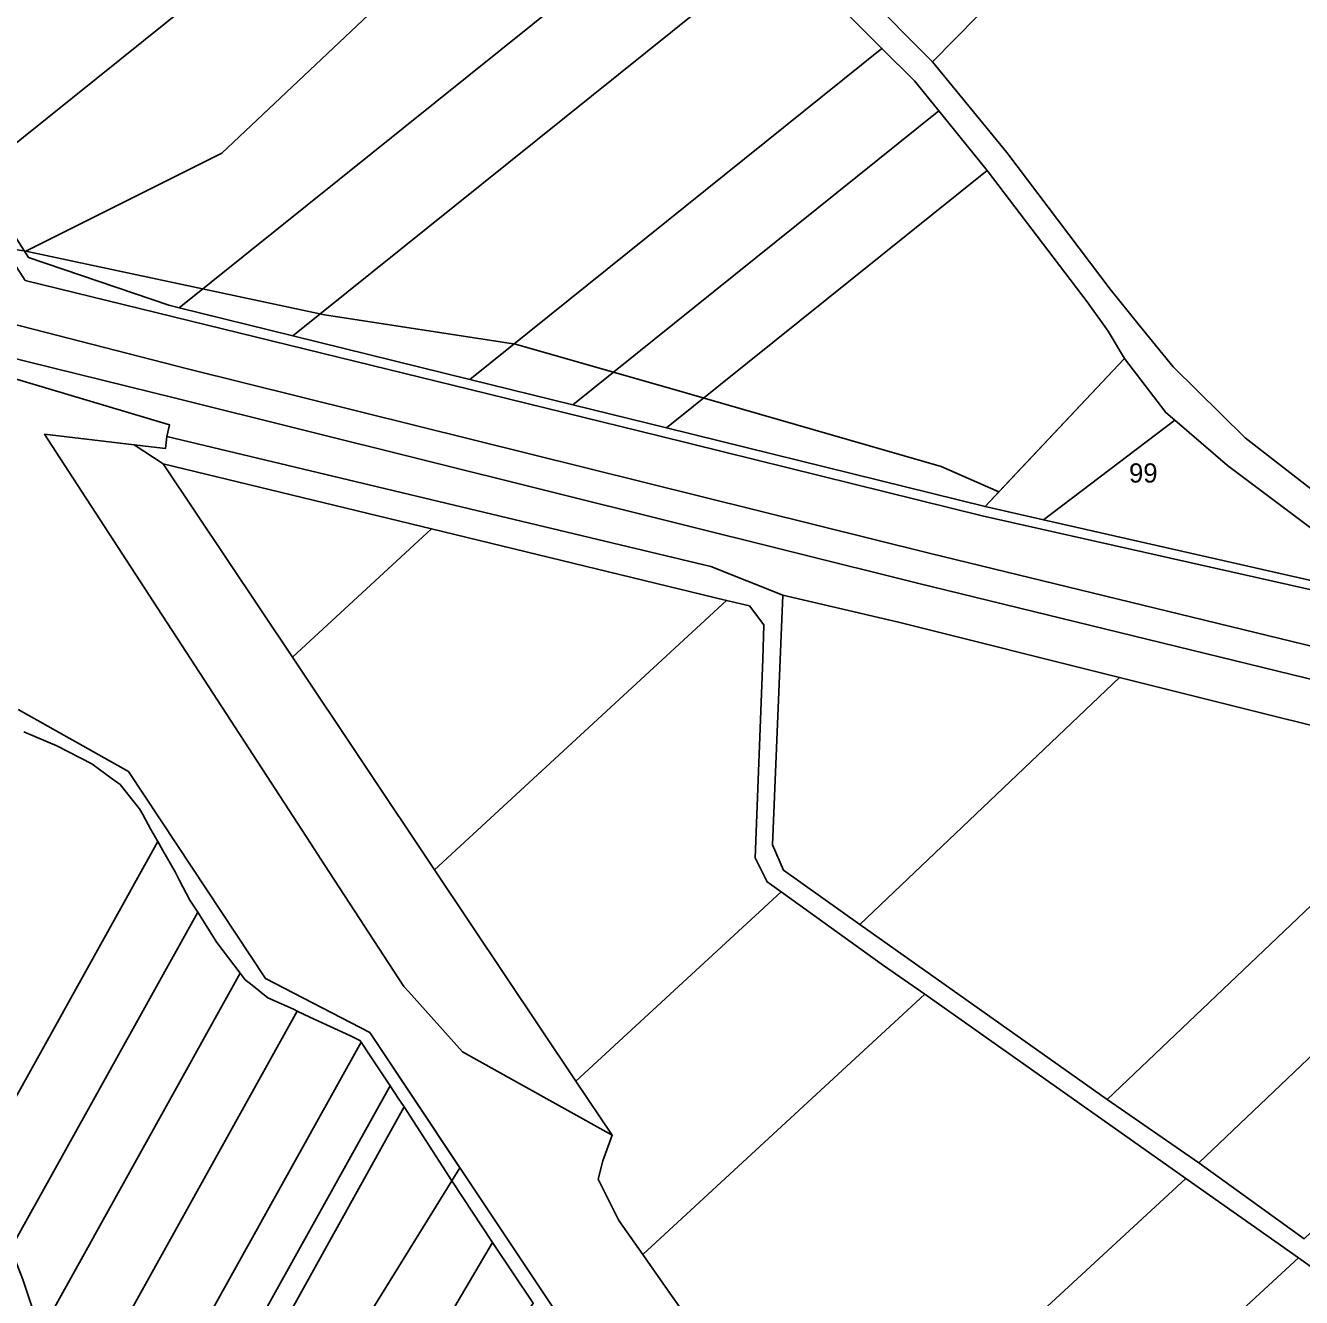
# Model space of a CAD drawing. Extents: x -545779 to -541342, y -1153413 to -1149956.
# Drawn here: x -543590.9 to -543258.3, y -1151443.3 to -1151111.8 of the extents above; entities that cross this region are included whole.
import ezdxf

# ---------------------------------------------------------------- set-up
doc = ezdxf.new("R2010")
doc.units = 0
for name, color, linetype in [('95560013', 7, 'Continuous'), ('95620013', 7, 'Continuous'), ('95630013', 7, 'Continuous'), ('95640013', 7, 'Continuous'), ('95660013', 7, 'Continuous')]:
    doc.layers.add(name, color=color, linetype=linetype)

msp = doc.modelspace()

# ---------------------------------------------------------------- linework, layer by layer
at = {"layer": '95560013'}
for points in [[(-543191.79, -1150924.95), (-543167.01, -1150930.79), (-543260.76, -1151026.06), (-543354.5, -1151121.33), (-543361.45, -1151114.32), (-543369.81, -1151105.87), (-543280.8, -1151015.41)], [(-543354.5, -1151121.33), (-543260.76, -1151026.06), (-543167.01, -1150930.79), (-542994.21, -1150971.47), (-543123.69, -1151103.06), (-543253.17, -1151234.66), (-543273, -1151219.27), (-543291.79, -1151200.81), (-543300.61, -1151189.88), (-543308.17, -1151180.51), (-543335.16, -1151144.92)], [(-543630.2, -1151097.88), (-543573.06, -1151053.18), (-543432.69, -1150939.38), (-543431.56, -1150970.58), (-543430.2, -1151002.57), (-543429.25, -1151010.65), (-543516.57, -1151080.72), (-543603.89, -1151150.79), (-543624.3, -1151109.73)], [(-543426.69, -1151032.45), (-543416.26, -1151059.6), (-543408.67, -1151071.25), (-543550.86, -1151185.35), (-543553.59, -1151184.67), (-543590.14, -1151172.28), (-543603.89, -1151150.79), (-543516.57, -1151080.72), (-543429.25, -1151010.65)], [(-543408.67, -1151071.25), (-543400.09, -1151084.43), (-543394.15, -1151090.66), (-543521.25, -1151192.65), (-543550.86, -1151185.35)], [(-543521.25, -1151192.65), (-543394.15, -1151090.66), (-543379.07, -1151106.47), (-543367.68, -1151117.79), (-543475.14, -1151204.03)], [(-543352.82, -1151134.09), (-543448.24, -1151210.67), (-543475.14, -1151204.03), (-543367.68, -1151117.79), (-543359.18, -1151126.23)], [(-543448.24, -1151210.67), (-543352.82, -1151134.09), (-543340.24, -1151149.63), (-543423.83, -1151216.7)], [(-543314.22, -1151183.8), (-543308.69, -1151191.46), (-543304.46, -1151198.58), (-543304.64, -1151198.78), (-543340.81, -1151237.2), (-543423.83, -1151216.7), (-543340.24, -1151149.63)], [(-543555.04, -1151226.04), (-543485.15, -1151242.98), (-543521.37, -1151276.39)], [(-543485.15, -1151242.98), (-543408.17, -1151261.65), (-543484.29, -1151331.85), (-543521.37, -1151276.39)], [(-543363.4, -1151267.31), (-543305.78, -1151281.7), (-543373.47, -1151346.07), (-543393.32, -1151331.96), (-543396.17, -1151325.33), (-543393.49, -1151260.23)], [(-543400.69, -1151328.68), (-543397.59, -1151335.01), (-543393.98, -1151337.61), (-543447.46, -1151386.93), (-543484.29, -1151331.85), (-543408.17, -1151261.65), (-543402.24, -1151263.09), (-543398.47, -1151268.03), (-543398.74, -1151276.93)], [(-543308.93, -1151391.67), (-543373.47, -1151346.07), (-543305.78, -1151281.7), (-543216.67, -1151303.95)], [(-543308.93, -1151391.67), (-543216.67, -1151303.95), (-543183.89, -1151312.04), (-543285.05, -1151408.23)], [(-543183.89, -1151312.04), (-543145.62, -1151321.51), (-543257.57, -1151427.96), (-543285.05, -1151408.23)], [(-543551.98, -1151332.36), (-543550.87, -1151334.45), (-543548.07, -1151339.72), (-543546.41, -1151342.35), (-543546.06, -1151342.91), (-543594.77, -1151430.54), (-543596.55, -1151425.99), (-543600.47, -1151417.38), (-543604.56, -1151410.97), (-543556.48, -1151324.47), (-543555.16, -1151326.78)], [(-543440.47, -1151407.63), (-543438.04, -1151401.02), (-543447.46, -1151386.93), (-543393.98, -1151337.61), (-543367.28, -1151356.8), (-543356.46, -1151364.23), (-543430.04, -1151432.08), (-543436.29, -1151423.22), (-543441.62, -1151412.47)], [(-543546.06, -1151342.91), (-543543.88, -1151346.35), (-543541.07, -1151350.8), (-543534.97, -1151358.76), (-543586.01, -1151450.59), (-543589.23, -1151445.86), (-543591.62, -1151438.6), (-543594.77, -1151430.54)], [(-543534.97, -1151358.76), (-543533.65, -1151360.47), (-543532.32, -1151361.53), (-543527.78, -1151365.16), (-543521.08, -1151368.18), (-543520.12, -1151368.63), (-543569.25, -1151457.02), (-543579.35, -1151456.9), (-543585.26, -1151451.7), (-543586.01, -1151450.59)], [(-543423.58, -1151441.25), (-543430.04, -1151432.08), (-543356.46, -1151364.23), (-543288.42, -1151412.25), (-543380.16, -1151496.84), (-543386.97, -1151488.23), (-543400.2, -1151471.61), (-543412.96, -1151456.3)], [(-543567.82, -1151457.04), (-543569.25, -1151457.02), (-543520.12, -1151368.63), (-543516.81, -1151370.19), (-543506.27, -1151375.14), (-543503.78, -1151376.31), (-543503.48, -1151376.77), (-543548.87, -1151458.44)], [(-543543.87, -1151459.07), (-543548.87, -1151458.44), (-543503.48, -1151376.77), (-543501.28, -1151380.06), (-543495.92, -1151388.1), (-543536.02, -1151460.25)], [(-543495.92, -1151388.1), (-543493.77, -1151391.33), (-543492.25, -1151393.62), (-543521.1, -1151445.52), (-543530.42, -1151462.28), (-543533.78, -1151460.57), (-543536.02, -1151460.25)], [(-543492.25, -1151393.62), (-543479.79, -1151412.85), (-543504.52, -1151452.78), (-543517.95, -1151446.9), (-543521.1, -1151445.52)], [(-543259.04, -1151432.91), (-543358.33, -1151524.47), (-543380.16, -1151496.84), (-543288.42, -1151412.25)], [(-543344.41, -1151542.05), (-543350.42, -1151534.47), (-543358.33, -1151524.47), (-543259.04, -1151432.91), (-543233.34, -1151451.27), (-543338.64, -1151548.36)]]:
    msp.add_lwpolyline(points, close=True, dxfattribs=at)
msp.add_lwpolyline([(-543591.36, -1151295.92), (-543582.77, -1151299.49), (-543573.62, -1151304.23), (-543568.35, -1151308.11), (-543566.28, -1151309.64), (-543562.63, -1151314.19), (-543561.21, -1151315.97), (-543560.4, -1151317.44), (-543558.29, -1151321.29), (-543556.48, -1151324.47), (-543604.56, -1151410.97)], dxfattribs=at)
at = {"layer": '95620013'}
for points in [[(-543340.81, -1151237.2), (-543304.64, -1151198.78), (-543304.46, -1151198.58), (-543293.67, -1151212.67), (-543291.35, -1151214.66), (-543325.56, -1151240.65)], [(-543325.56, -1151240.65), (-543291.35, -1151214.66), (-543277.58, -1151226.45), (-543258.78, -1151240.57), (-543254.3, -1151243.94), (-543225.5, -1151263.28)], [(-543504.52, -1151452.78), (-543479.79, -1151412.85), (-543469.2, -1151428.92), (-543498.42, -1151478.56), (-543515.19, -1151470.03)], [(-543488.42, -1151484.25), (-543498.42, -1151478.56), (-543469.2, -1151428.92), (-543458.58, -1151444.8), (-543485.9, -1151485.95)]]:
    msp.add_lwpolyline(points, close=True, dxfattribs=at)
at = {"layer": '95630013'}
for points in [[(-543254.3, -1151243.94), (-543258.78, -1151240.57), (-543277.58, -1151226.45), (-543291.35, -1151214.66), (-543293.67, -1151212.67), (-543304.46, -1151198.58), (-543308.69, -1151191.46), (-543314.22, -1151183.8), (-543340.24, -1151149.63), (-543352.82, -1151134.09), (-543359.18, -1151126.23), (-543367.68, -1151117.79), (-543379.07, -1151106.47)], [(-543369.81, -1151105.87), (-543361.45, -1151114.32), (-543354.5, -1151121.33), (-543335.16, -1151144.92), (-543308.17, -1151180.51), (-543300.61, -1151189.88), (-543291.79, -1151200.81), (-543273, -1151219.27), (-543253.17, -1151234.66)], [(-543598.49, -1151188.54), (-543548.68, -1151201.25), (-543354.98, -1151249.39), (-543176.13, -1151292.96)], [(-543178.39, -1151301.1), (-543358.41, -1151257.17), (-543551.46, -1151209.01), (-543596.99, -1151197.82)]]:
    msp.add_lwpolyline(points, dxfattribs=at)
at = {"layer": '95640013'}
for points in [[(-543591.06, -1151178.24), (-543593.23, -1151174.88), (-543607.02, -1151153.49), (-543634.9, -1151097.4), (-543628.2, -1151092.28), (-543630.2, -1151097.88), (-543624.3, -1151109.73), (-543603.89, -1151150.79), (-543590.14, -1151172.28), (-543553.59, -1151184.67), (-543550.86, -1151185.35), (-543521.25, -1151192.65), (-543475.14, -1151204.03), (-543448.24, -1151210.67), (-543423.83, -1151216.7), (-543340.81, -1151237.2), (-543325.56, -1151240.65), (-543225.5, -1151263.28), (-543213.98, -1151267.2), (-543204.67, -1151270.37), (-543341.53, -1151239.59), (-543425.84, -1151218.75), (-543474.99, -1151206.7)], [(-543555.31, -1151265.47), (-543582.01, -1151224.44), (-543585.98, -1151218.34), (-543562.6, -1151221.1), (-543555.04, -1151226.04), (-543521.37, -1151276.39), (-543484.29, -1151331.85), (-543447.46, -1151386.93), (-543438.04, -1151401.02), (-543463.51, -1151386.83), (-543477.04, -1151379.29), (-543491.12, -1151363.58), (-543492.35, -1151362.21), (-543512.99, -1151330.5), (-543517.62, -1151323.38), (-543551.39, -1151271.49)]]:
    msp.add_lwpolyline(points, close=True, dxfattribs=at)
for points in [[(-543591.06, -1151178.24), (-543474.99, -1151206.7), (-543425.84, -1151218.75), (-543341.53, -1151239.59), (-543204.67, -1151270.37)], [(-543176.13, -1151292.96), (-543354.98, -1151249.39), (-543548.68, -1151201.25), (-543598.49, -1151188.54)], [(-543596.99, -1151197.82), (-543551.46, -1151209.01), (-543358.41, -1151257.17), (-543178.39, -1151301.1)], [(-543216.67, -1151303.95), (-543305.78, -1151281.7), (-543363.4, -1151267.31), (-543393.49, -1151260.23), (-543412.29, -1151252.82), (-543554.12, -1151218.94), (-543553.4, -1151215.92), (-543601.53, -1151201.58)], [(-543601.53, -1151201.58), (-543553.4, -1151215.92), (-543554.12, -1151218.94), (-543554.5, -1151222.05), (-543562.6, -1151221.1), (-543585.98, -1151218.34), (-543582.01, -1151224.44), (-543555.31, -1151265.47), (-543551.39, -1151271.49), (-543517.62, -1151323.38), (-543512.99, -1151330.5), (-543492.35, -1151362.21), (-543491.12, -1151363.58), (-543477.04, -1151379.29), (-543463.51, -1151386.83), (-543438.04, -1151401.02), (-543440.47, -1151407.63), (-543441.62, -1151412.47), (-543436.29, -1151423.22), (-543430.04, -1151432.08), (-543423.58, -1151441.25), (-543412.96, -1151456.3)], [(-543233.34, -1151451.27), (-543259.04, -1151432.91), (-543288.42, -1151412.25), (-543356.46, -1151364.23), (-543367.28, -1151356.8), (-543393.98, -1151337.61), (-543397.59, -1151335.01), (-543400.69, -1151328.68), (-543398.74, -1151276.93), (-543398.47, -1151268.03), (-543402.24, -1151263.09), (-543408.17, -1151261.65), (-543485.15, -1151242.98), (-543555.04, -1151226.04), (-543562.6, -1151221.1), (-543554.5, -1151222.05), (-543554.12, -1151218.94), (-543412.29, -1151252.82), (-543393.49, -1151260.23), (-543396.17, -1151325.33), (-543393.32, -1151331.96), (-543373.47, -1151346.07), (-543308.93, -1151391.67), (-543285.05, -1151408.23), (-543257.57, -1151427.96)], [(-543592.86, -1151290.06), (-543564.09, -1151306.26), (-543551.48, -1151325.26), (-543528.41, -1151360.19), (-543501.2, -1151374.23), (-543466.03, -1151427.04), (-543430.64, -1151480.07)], [(-543430.64, -1151480.07), (-543466.03, -1151427.04), (-543501.2, -1151374.23), (-543528.41, -1151360.19), (-543551.48, -1151325.26), (-543564.09, -1151306.26), (-543592.86, -1151290.06)], [(-543458.58, -1151444.8), (-543469.2, -1151428.92), (-543479.79, -1151412.85), (-543492.25, -1151393.62), (-543493.77, -1151391.33), (-543495.92, -1151388.1), (-543501.28, -1151380.06), (-543503.48, -1151376.77), (-543503.78, -1151376.31), (-543506.27, -1151375.14), (-543516.81, -1151370.19), (-543520.12, -1151368.63), (-543521.08, -1151368.18), (-543527.78, -1151365.16), (-543532.32, -1151361.53), (-543533.65, -1151360.47), (-543534.97, -1151358.76), (-543541.07, -1151350.8), (-543543.88, -1151346.35), (-543546.06, -1151342.91), (-543546.41, -1151342.35), (-543548.07, -1151339.72), (-543550.87, -1151334.45), (-543551.98, -1151332.36), (-543555.16, -1151326.78), (-543556.48, -1151324.47), (-543558.29, -1151321.29), (-543560.4, -1151317.44), (-543561.21, -1151315.97), (-543562.63, -1151314.19), (-543566.28, -1151309.64), (-543568.35, -1151308.11), (-543573.62, -1151304.23), (-543582.77, -1151299.49), (-543591.36, -1151295.92)], [(-543591.62, -1151438.6), (-543589.23, -1151445.86)]]:
    msp.add_lwpolyline(points, dxfattribs=at)
at = {"layer": '95660013'}
for points in [[(-543266.368, -1150723.515), (-543301.776, -1150762.751), (-543339.096, -1150807.729), (-543369.721, -1150846.008), (-543390.774, -1150875.674), (-543412.204, -1150907.776), (-543418.583, -1150934.572), (-543427.515, -1150971.575), (-543447.932, -1151030.269), (-543464.518, -1151065.996), (-543493.866, -1151101.723), (-543539.8, -1151145.106), (-543590.84, -1151170.626), (-543596.525, -1151169.769)], [(-543254.3, -1151243.94), (-543258.78, -1151240.57), (-543277.58, -1151226.45), (-543291.35, -1151214.66), (-543293.67, -1151212.67), (-543304.46, -1151198.58), (-543304.64, -1151198.78), (-543337.186, -1151233.351), (-543352.232, -1151226.768), (-543418.583, -1151207.629), (-543463.243, -1151194.869), (-543513.006, -1151187.213), (-543590.84, -1151170.626), (-543539.8, -1151145.106), (-543493.866, -1151101.723)], [(-543596.525, -1151169.769), (-543590.84, -1151170.626), (-543513.006, -1151187.213), (-543463.243, -1151194.869), (-543418.583, -1151207.629), (-543352.232, -1151226.768), (-543337.186, -1151233.351), (-543340.81, -1151237.2), (-543325.56, -1151240.65), (-543225.5, -1151263.28)], [(-543412.96, -1151456.3), (-543423.58, -1151441.25), (-543430.04, -1151432.08), (-543436.29, -1151423.22), (-543441.62, -1151412.47), (-543440.47, -1151407.63), (-543438.04, -1151401.02), (-543463.51, -1151386.83), (-543477.04, -1151379.29), (-543491.12, -1151363.58), (-543492.35, -1151362.21), (-543512.99, -1151330.5), (-543517.62, -1151323.38), (-543551.39, -1151271.49), (-543555.31, -1151265.47), (-543582.01, -1151224.44), (-543585.98, -1151218.34), (-543562.6, -1151221.1), (-543554.5, -1151222.05), (-543554.12, -1151218.94), (-543553.4, -1151215.92), (-543601.53, -1151201.58)], [(-543601.53, -1151201.58), (-543553.4, -1151215.92), (-543554.12, -1151218.94), (-543554.5, -1151222.05), (-543562.6, -1151221.1), (-543585.98, -1151218.34), (-543582.01, -1151224.44), (-543555.31, -1151265.47), (-543551.39, -1151271.49), (-543517.62, -1151323.38), (-543512.99, -1151330.5), (-543492.35, -1151362.21), (-543491.12, -1151363.58), (-543477.04, -1151379.29), (-543463.51, -1151386.83), (-543438.04, -1151401.02), (-543440.47, -1151407.63), (-543441.62, -1151412.47), (-543436.29, -1151423.22), (-543430.04, -1151432.08), (-543423.58, -1151441.25), (-543412.96, -1151456.3)], [(-543592.86, -1151290.06), (-543564.09, -1151306.26), (-543551.48, -1151325.26), (-543528.41, -1151360.19), (-543501.2, -1151374.23), (-543477.713, -1151409.497), (-543479.79, -1151412.85), (-543504.52, -1151452.78)], [(-543504.52, -1151452.78), (-543479.79, -1151412.85), (-543477.713, -1151409.497), (-543501.2, -1151374.23), (-543528.41, -1151360.19), (-543551.48, -1151325.26), (-543564.09, -1151306.26), (-543592.86, -1151290.06)]]:
    msp.add_lwpolyline(points, dxfattribs=at)
msp.add_lwpolyline([(-543340.81, -1151237.2), (-543337.186, -1151233.351), (-543304.64, -1151198.78), (-543304.46, -1151198.58), (-543293.67, -1151212.67), (-543291.35, -1151214.66), (-543277.58, -1151226.45), (-543258.78, -1151240.57), (-543254.3, -1151243.94), (-543225.5, -1151263.28), (-543325.56, -1151240.65)], close=True, dxfattribs=at)

# ---------------------------------------------------------------- texts
msp.add_text('99', height=5, rotation=360, dxfattribs=at).set_placement((-543303.261, -1151230.93))

doc.saveas('drawing.dxf')
